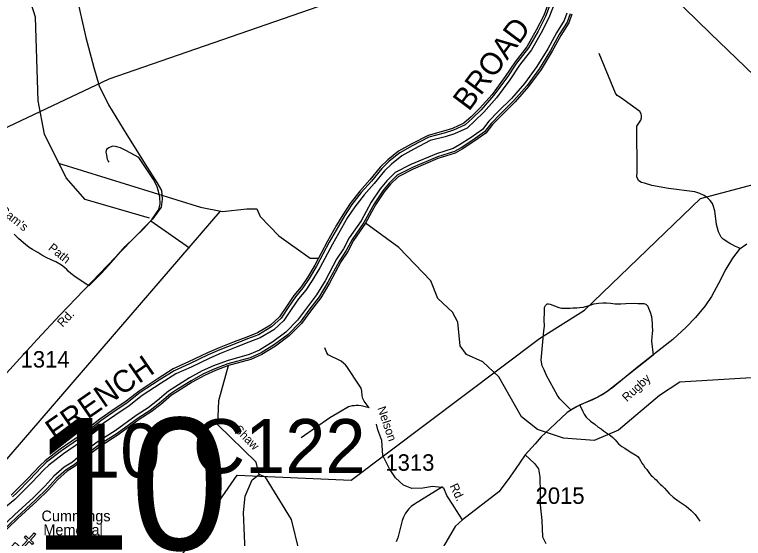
# Model space of a CAD drawing. Extents: x 884530 to 1028605, y 526725 to 653634.
# Drawn here: x 938802 to 944336, y 599486 to 603462 of the extents above; entities that cross this region are included whole.
import ezdxf

# ---------------------------------------------------------------- set-up
doc = ezdxf.new("R2010")
doc.units = 0
for name, color, linetype in [('Exist Cultural Church CELL', 7, 'Continuous'), ('Exist Cultural Church Label', 7, 'Continuous'), ('Exist Hydrographic Bay Label', 7, 'Continuous'), ('Exist Hydrographic Buffer Line', 7, 'Continuous'), ('Exist Hydrographic Creek Single Shore', 7, 'Continuous'), ('Exist Hydrographic Creek Single Shore Label', 7, 'Continuous'), ('Exist Hydrographic Misc Water Feature', 7, 'Continuous'), ('Exist Hydrographic River Shore Label', 7, 'Continuous'), ('Exist Road Non-System Type 51', 7, 'Continuous'), ('Exist Road Non-System Type 51 Label', 7, 'Continuous'), ('Exist Road Secondary Structure Culvert Number Label', 7, 'Continuous'), ('Exist Road Secondary Structure Standard Bridge Number Label', 7, 'Continuous'), ('Exist Road Secondary Type 51 Attributed', 7, 'Continuous'), ('Exist Road Secondary Type 51 Label', 7, 'Continuous'), ('Exist Road Secondary Type 51 Number Label', 7, 'Continuous'), ('Exist Utilities Electrical Transmission Line', 7, 'Continuous'), ('Raster_Level_0', 7, 'Continuous')]:
    doc.layers.add(name, color=color, linetype=linetype)

msp = doc.modelspace()

# ---------------------------------------------------------------- linework, layer by layer
at = {"layer": 'Exist Cultural Church CELL'}
msp.add_lwpolyline([(938806.1, 599454.1), (938848.2, 599415.8), (938899.6, 599472), (938876, 599493.6), (938886.8, 599505.4), (938910.4, 599483.8), (938951, 599528.2), (938962.8, 599517.4), (938922.2, 599473), (938945.8, 599451.4), (938935.1, 599439.6), (938911.4, 599461.2), (938860.1, 599405), (938902.6, 599366), (938830.7, 599287.4), (938734.3, 599375.6)], close=True, dxfattribs=at)
at = {"layer": 'Exist Hydrographic Bay Label'}
for points in [[(942861.5, 603565), (942819.8, 603453.8), (942762.7, 603343.9), (942692.1, 603217.6), (942601.5, 603102.1), (942527.5, 602990.4), (942427.4, 602856.1), (942332.8, 602749.4), (942267.9, 602686.1), (942213.6, 602636.6), (942127.9, 602597.6), (942059, 602576), (941941.6, 602544.9), (941813.5, 602478.9), (941717.2, 602424.3), (941636.5, 602359.4), (941578.7, 602303.5), (941498.9, 602207.1), (941422.8, 602120.4), (941350.6, 602028.5), (941294.4, 601942.8), (941247.1, 601862.9), (941178.3, 601741.3)], [(943033.2, 603463.6), (943009.1, 603399.1), (942948.9, 603303.8), (942882.9, 603183.3), (942799, 603045.3), (942704.2, 602914.9), (942602.3, 602799.4), (942500.1, 602698.6), (942431.4, 602626.6), (942380.3, 602562.1), (942290, 602497.7), (942200.2, 602439.3), (942147.6, 602410.6), (942015.8, 602368.8)], [(942015.8, 602368.8), (941827.5, 602288.9), (941714.9, 602231.1), (941655.8, 602174), (941608, 602116.1), (941542.9, 602017.7), (941466.1, 601878.1)], [(941466.1, 601878.1), (941376, 601747.8), (941331.1, 601663.7), (941280, 601585.9), (941192.4, 601422.9), (941126.1, 601312.9), (941055.2, 601221.3), (940980.1, 601117.5), (940887.4, 601022.4), (940783.2, 600945.9), (940680, 600881.6), (940594.5, 600844.6), (940425.3, 600797.4)], [(941178.3, 601741.3), (941081.9, 601560.8), (941025.9, 601466.5), (940978, 601395.7), (940922.1, 601328.5), (940872.4, 601253.7), (940813, 601168.2), (940744.3, 601104), (940646.7, 601045.7), (940565.7, 601014), (940469.8, 600976.6), (940354.3, 600931.5), (940265.4, 600893.5), (940123.3, 600825.3), (940005.9, 600771.9), (939891.2, 600699.5), (939746.7, 600604.5), (939647.9, 600526.3), (939539.5, 600454.2), (939448.5, 600391.1), (939354.4, 600317.3), (939277.2, 600251.1), (939148.7, 600162.3), (939032.8, 600075.2), (938994.1, 600036.3), (938903.2, 599940.9), (938809.9, 599846.1), (938775.8, 599813.7)], [(940425.3, 600797.4), (940326.5, 600759.7), (940243.3, 600723.3), (940149.5, 600671.3), (940038.4, 600602), (939993.3, 600572.8), (939911.6, 600503.2), (939837.8, 600445.4), (939747.2, 600387.9), (939587.1, 600271.7), (939451.7, 600184), (939359.3, 600114.9), (939263, 600034.4), (939201.4, 599996.6), (939127, 599930.4), (939058.5, 599855), (938970.7, 599767.7), (938826.9, 599636.4), (938666.3, 599486.3)]]:
    msp.add_lwpolyline(points, dxfattribs=at)
at = {"layer": 'Exist Hydrographic Buffer Line'}
for points in [[(942876.2, 603560.8), (942833.7, 603447.6), (942776.1, 603336.7), (942704.8, 603209.1), (942613.8, 603093.2), (942540, 602981.7), (942439.3, 602846.5), (942343.9, 602738.9), (942278.4, 602675), (942222, 602623.7), (942133.3, 602583.3), (942063.3, 602561.4), (941947.1, 602530.6), (941820.8, 602465.5), (941725.8, 602411.7), (941646.6, 602348), (941589.8, 602293.2), (941510.5, 602197.2), (941434.5, 602110.7), (941362.9, 602019.6), (941307.3, 601934.7), (941260.3, 601855.3), (941191.5, 601733.8)], [(942902.7, 603553.1), (942858.9, 603436.4), (942800.3, 603323.6), (942727.8, 603193.8), (942636.2, 603077.1), (942562.5, 602965.8), (942460.6, 602829.1), (942363.8, 602719.9), (942297.2, 602655), (942237.4, 602600.5), (942143.2, 602557.5), (942070.9, 602534.9), (941957.1, 602504.8), (941833.9, 602441.3), (941741.3, 602388.8), (941664.8, 602327.3), (941610.1, 602274.4), (941531.5, 602179.4), (941455.7, 602093.1), (941385.3, 602003.5), (941330.7, 601920.2), (941284.1, 601841.5), (941215.5, 601720.2)], [(942995.4, 603472.3), (942974.5, 603416.3), (942915.7, 603323.4), (942849.6, 603202.6), (942767, 603066.7), (942674.1, 602939), (942574.3, 602825.8), (942472.6, 602725.6), (942402.3, 602651.9), (942353.5, 602590.3), (942268.3, 602529.6), (942180.5, 602472.4), (942132.4, 602446.2), (942004.2, 602405.5)], [(943020, 603466.6), (942997, 603405.2), (942937.3, 603310.6), (942871.3, 603190), (942787.8, 603052.8), (942693.7, 602923.3), (942592.5, 602808.6), (942490.5, 602708), (942421.2, 602635.5), (942370.9, 602572), (942282.4, 602508.9), (942193.3, 602450.9), (942142.2, 602423.1), (942011.7, 602381.7)], [(942004.2, 602405.5), (941811.2, 602323.7), (941692.3, 602262.6), (941627.6, 602200.1), (941577.1, 602139), (941510, 602037.6), (941432.5, 601896.6)], [(942011.7, 602381.7), (941821.8, 602301.1), (941707, 602242.1), (941645.9, 602183.2), (941597.2, 602124.1), (941531.4, 602024.7), (941454.4, 601884.6)], [(941432.5, 601896.6), (941343.4, 601767.7), (941298.3, 601683.2), (941247.2, 601605.5), (941159.2, 601441.8), (941094.6, 601334.5), (941024.6, 601244.1), (940950.9, 601142.1), (940862.3, 601051.3), (940761.8, 600977.5), (940662.2, 600915.5), (940581.8, 600880.6), (940415.1, 600834.1)], [(941454.4, 601884.6), (941364.6, 601754.7), (941319.7, 601670.5), (941268.5, 601592.8), (941180.8, 601429.5), (941115.1, 601320.4), (941044.5, 601229.3), (940969.9, 601126.1), (940878.6, 601032.5), (940775.7, 600957), (940673.8, 600893.5), (940590.1, 600857.2), (940421.7, 600810.3)], [(941215.5, 601720.2), (941119.1, 601539.8), (941062, 601443.6), (941012.2, 601370), (940956.5, 601303), (940907.8, 601229.7), (940845.5, 601140.1), (940770.1, 601069.7), (940665.6, 601007.2), (940581.3, 600974.2), (940485.4, 600936.8), (940370.5, 600891.9), (940283, 600854.5), (940141.4, 600786.6), (940026.3, 600734.2), (939914.3, 600663.6), (939771.7, 600569.8), (939673, 600491.7), (939563.5, 600418.8), (939473.8, 600356.7), (939381.5, 600284.2), (939303.3, 600217.2), (939173.8, 600127.6), (939061, 600042.9), (939024.7, 600006.5), (938933.9, 599911.2), (938839.8, 599815.7), (938804.1, 599781.7), (938733.8, 599723.9)], [(941191.5, 601733.8), (941095.2, 601553.3), (941038.7, 601458.4), (940990.2, 601386.6), (940934.4, 601319.4), (940885, 601245.2), (940824.6, 601158.2), (940753.5, 601091.8), (940653.4, 601032), (940571.3, 600999.9), (940475.4, 600962.4), (940360.1, 600917.4), (940271.6, 600879.6), (940129.7, 600811.5), (940013.2, 600758.4), (939899.4, 600686.7), (939755.6, 600592.1), (939656.8, 600514), (939548.1, 600441.6), (939457.5, 600378.8), (939364, 600305.5), (939286.5, 600239), (939157.7, 600150), (939042.9, 600063.7), (939005, 600025.7), (938914.1, 599930.3), (938820.5, 599835.3), (938785.8, 599802.3)], [(940415.1, 600834.1), (940312.1, 600794.9), (940226.4, 600757.4), (940130.2, 600704.1), (940018.1, 600634), (939970.6, 600603.3), (939887.6, 600532.6), (939815.8, 600476.5), (939725.8, 600419.3), (939565.6, 600303), (939429.9, 600215.2), (939335.8, 600144.7), (939240.8, 600065.4), (939178.6, 600027.2), (939100.3, 599957.4), (939031, 599881.3), (938944.5, 599795.2), (938801.1, 599664.3), (938640.3, 599514)], [(940421.7, 600810.3), (940321.4, 600772), (940237.4, 600735.3), (940142.7, 600682.8), (940031.3, 600613.2), (939985.3, 600583.4), (939903.2, 600513.5), (939830.1, 600456.3), (939739.7, 600398.9), (939579.6, 600282.7), (939444.1, 600194.9), (939351.1, 600125.3), (939255.3, 600045.3), (939193.4, 600007.3), (939117.7, 599939.9), (939048.9, 599864.2), (938961.5, 599777.4), (938817.9, 599646.1), (938657.2, 599496)]]:
    msp.add_lwpolyline(points, dxfattribs=at)
at = {"layer": 'Exist Hydrographic Creek Single Shore'}
for points in [[(939825.1, 601917.1), (939337.3, 602058.3), (939192.9, 602222), (939029.8, 602553.5), (938980.6, 602807.1), (938961.5, 603440.8), (938894, 603652.3), (938832, 603778.2), (938607.9, 604045.2), (938502.2, 604122.8), (938083.6, 604305.1), (937355.4, 604457.6), (937085.2, 604600.9), (936893.6, 604608), (936597, 604709.1), (936265.2, 604755.1), (935718.2, 605081.2), (935429.2, 605159.1), (934980.7, 605443.8)], [(939136, 602334.5), (940213.1, 602000.5), (940380, 601967.9), (940564.9, 601986), (940641.1, 601986), (940666.5, 601927.9), (940807.9, 601782.8), (941047.3, 601612.2), (941109, 601612.2)], [(938351.1, 599435.9), (938336.6, 599483.1), (938348.1, 599555), (938392.5, 599626.4), (938476.5, 599748.7), (938552.7, 599868.4), (940361.8, 601967.9)], [(939836, 601895.3), (940129.7, 601692)], [(940657.9, 599971.4), (940636.1, 600063.8), (940346.2, 600348.6), (940352.8, 600532.2), (940425.3, 600797.4)], [(940429.8, 596868.3), (940324.6, 597254.9), (940338.4, 597415.5), (940395.8, 597602.9), (940409.7, 597959.7), (940469.1, 598102), (940505.2, 598274.7), (940595.9, 598501.9), (940777.7, 598680.5), (940766.9, 598844.5), (940667.6, 598940), (940567, 599088.4), (940554.5, 599328.8), (940539, 599681.8), (940552.1, 599806.3), (940606.4, 599929.8), (940657.9, 599971.4)], [(944279.7, 596872.5), (944318.7, 597024.5), (944253.6, 597146.1), (944101.8, 597241.7), (943949.9, 597385), (943798, 597493.6), (943706.8, 597541.4), (942989.5, 597531.4), (942717.5, 597642.9), (942524.9, 597864), (942441.8, 597941.5), (942072.2, 598253), (941833, 598326.8), (941457.7, 598586.1), (941261.4, 598801.3), (941111.8, 598983.8), (940962.3, 599391.1), (940904.1, 599628.5), (940707.4, 599950.8), (940657.9, 599971.4)]]:
    msp.add_lwpolyline(points, dxfattribs=at)
at = {"layer": 'Exist Hydrographic Misc Water Feature'}
msp.add_lwpolyline([(944394.9, 600703.7), (943851.9, 600672), (943698.1, 600570), (943388.3, 600307.1), (943202.3, 600228.8), (942969.3, 600246.7), (942771.6, 600313), (942649.8, 600407.3), (942477.5, 600712.7), (942356.3, 600826.7), (942233.3, 600881.7), (942185.6, 600948.2), (942166.9, 601125.8), (942128, 601202.1), (942015, 601306.1), (941961.5, 601441.8), (941720.2, 601692.7), (941466.1, 601878.1)], dxfattribs=at)
at = {"layer": 'Exist Road Non-System Type 51'}
for points in [[(944312.7, 601686.7), (944275.4, 601701.6), (944253.8, 601712.9), (944231.8, 601725), (944182.1, 601758), (944167, 601772.9), (944156, 601793), (944146.5, 601813.5), (944132.5, 601867.7), (944118.8, 601971.5), (944105.2, 602012.3), (944100, 602028), (944083.3, 602050), (944062.1, 602070.1), (944038.2, 602087.8), (944005.7, 602102.4), (943965.9, 602115), (943766.9, 602142.2), (943639, 602164.2), (943583.6, 602180.9), (943561.5, 602188.3), (943542.7, 602199.8), (943531.3, 602217.7), (943525.9, 602231.3), (943528, 602268), (943526.9, 602614.8), (943557.1, 602660.4), (943561.3, 602677.5), (943561.3, 602692.6), (943559.8, 602707.5), (943548.8, 602725.4), (943402.9, 602833.1), (943377.5, 602846.5), (943364, 602864.5), (943239.9, 603164.9)], [(939744.7, 602376.8), (939647.5, 602430.8), (939619.9, 602441.7), (939605.8, 602449.6), (939586.8, 602455.9), (939567.1, 602459.9), (939545.9, 602462.2), (939516.8, 602450.5), (939500.7, 602436.5), (939497.4, 602429.9), (939495.5, 602418.1), (939496.3, 602407.1), (939499.4, 602393.7), (939503.3, 602377.2), (939505, 602364.5), (939510.4, 602355.1), (939512.8, 602348.8), (939516.8, 602341)], [(939366, 601403.7), (939458.7, 601497.1), (939517.9, 601559.8), (939641.5, 601701.2), (939781.9, 601838), (939845.5, 601910), (939896.6, 601981.4), (939907.3, 602024.1), (939905.2, 602076.2), (939895.5, 602121.6), (939880.6, 602162), (939855.8, 602210.3), (939744.7, 602376.8)], [(939366, 601403.7), (939262, 601472.3), (939228.4, 601496.1), (939207.6, 601515), (939197.7, 601526.4), (939181.4, 601541.8), (939158.3, 601559.5), (939113.9, 601585.7), (939078.5, 601601.3), (939042.3, 601617.6), (939009.7, 601636.3), (938978.1, 601655.8), (938955.2, 601669.3), (938937.9, 601679.2), (938913.7, 601694.7), (938883.5, 601716.3), (938834.1, 601758.9), (938799.8, 601794.2)], [(943025.7, 600462.1), (942966.7, 600518.7), (942941.3, 600546.3), (942923, 600571.6), (942840.2, 600723.2), (942821.9, 600764.6), (942808.1, 600794.5), (942801.2, 600838.1), (942821.4, 601060.1), (942824.1, 601095.5), (942822.2, 601143.5), (942821.9, 601150.6), (942824.1, 601196.6), (942826.4, 601237.9), (942831.8, 601253.1), (942844.9, 601265.6), (942855.6, 601266.6), (942868.5, 601264.2), (942934, 601237.4), (942943.4, 601235.4), (942955.6, 601233.4), (943019.5, 601233.4), (943040.2, 601235.7), (943060.8, 601235.3), (943070.1, 601235.7), (943092.3, 601237.8), (943120.2, 601241), (943164.5, 601252.5), (943200.7, 601267), (943234.4, 601272.2), (943268.1, 601274.7), (943296.6, 601274.7), (943325.2, 601272.2), (943362.2, 601267.2), (943404.5, 601267), (943443.2, 601267.6), (943508.7, 601270.6), (943533.6, 601269.7), (943556.8, 601269.2), (943580, 601268.5), (943593.7, 601263.9), (943602.9, 601256.8), (943609.6, 601248), (943615.3, 601232.5), (943627.8, 601203.5), (943636.6, 601170.4), (943641.1, 601142.7), (943642.3, 601119), (943642.5, 601094.4), (943644.5, 601065.7), (943642.6, 601038.8), (943641.1, 601018.1), (943637.9, 600983.2), (943650.6, 600876.8)], [(941494.1, 600477.2), (941455.4, 600528.3), (941445.8, 600547), (941439.7, 600566.7), (941438.6, 600604.2), (941432.9, 600624.9), (941424.4, 600642), (941324.9, 600790.2), (941313.4, 600804.2), (941301.3, 600813.7), (941280.5, 600830.2), (941262.4, 600839.9), (941201.8, 600868.1), (941181.8, 600880.3), (941171.7, 600893.9), (941157.5, 600931.1)], [(943650.6, 600876.8), (943393.6, 600673.1), (943333.3, 600624.9), (943299.4, 600597.8), (943259.4, 600574.4), (943229.9, 600558.5), (943190, 600541.2), (943144, 600520.9), (943094.6, 600498)], [(941494.1, 600477.2), (941433.6, 600491.9), (941412.8, 600493.3), (941394.2, 600494), (941380, 600492.6), (941365.6, 600491.1), (941355.7, 600489.7), (941337.7, 600483.3), (941268.7, 600445.2), (941255.6, 600437.5), (941194.2, 600400.5), (940976.9, 600249.9)], [(943094.6, 600498), (943061.8, 600483.1), (943025.7, 600462.1)], [(943094.6, 600498), (943115.2, 600447.8), (943125.7, 600427.8), (943141.2, 600406.9), (943174.9, 600375.3), (943207.7, 600351.8), (943233.2, 600331.2), (943254.9, 600317.3), (943272.2, 600303), (943325.6, 600266.6), (943343.9, 600252.5), (943361.9, 600232.9), (943386, 600202.7), (943412.3, 600183.1), (943435, 600169.6), (943476.4, 600143.2), (943518.7, 600118.3), (943533, 600106.2), (943546.5, 600088.9), (943556.4, 600071.5), (943565.4, 600056.5), (943577.5, 600040.6), (943588.1, 600024.1), (943601.6, 600008.2), (943613, 599993.1), (943621.9, 599978), (943634, 599964.5), (943645.3, 599955.4), (943660.5, 599940.4), (943673.5, 599930.9), (943686.7, 599915.4), (943703.9, 599897.9), (943719.2, 599883.6), (943735.8, 599866.5), (943772, 599827.3), (943802.9, 599798.6), (943841.3, 599771.5), (943900.9, 599730.8), (943937.8, 599698.4), (943970.3, 599666.8), (944004.8, 599616.6)], [(942049.8, 599877.2), (941837.1, 599744.9), (941813, 599728.6), (941795.3, 599709.3), (941770.8, 599676.9), (941762.6, 599663.4), (941753.6, 599646), (941744, 599622), (941712.8, 599489.3), (941698.4, 599459.7)]]:
    msp.add_lwpolyline(points, dxfattribs=at)
at = {"layer": 'Exist Road Secondary Type 51 Attributed'}
for points in [[(939270.6, 603612.8), (939342.5, 603288.1), (939402.9, 603060.3), (939444.7, 602920.9), (939514.3, 602776.8), (939653.7, 602549), (939811.6, 602298), (939881.3, 602186.5), (939918.5, 602126.1), (939923.1, 602061), (939913.8, 602000.6), (939848.8, 601907.6), (939686.2, 601744.9), (939148.5, 601181.7), (938972, 600995.8), (938605.1, 600596), (938317.1, 600289.3), (938173.1, 600154.5), (938089.5, 600038.3), (938033.7, 599940.7), (938033.7, 599843.1), (938052.3, 599768.7), (938103.1, 599712.8)], [(944360.4, 601719.1), (944302.5, 601678.2), (944252.6, 601613.6), (944201.7, 601529.3), (944145.7, 601421.5), (944093.5, 601322.8), (944044.5, 601250.2), (943971.5, 601162.4), (943901.4, 601089), (943799.5, 600996.6), (943661.4, 600886.8), (943529.5, 600783.4), (943418.1, 600690.7), (943343.5, 600631), (943267.6, 600577.4), (943184.2, 600535.1), (943095.9, 600499), (943038.6, 600465.8), (942997.4, 600440.4), (942866.3, 600317.9), (942800.5, 600257.2), (942754.3, 600203.4), (942679, 600121)], [(942203, 599627.6), (942156.9, 599697.7), (942131.4, 599737.5), (942084.6, 599810.2), (942061.8, 599867.6), (942044.2, 599871.1), (941974.1, 599880.4), (941901.1, 599867.6), (941818.4, 599864.4), (941754.7, 599889.8), (941694.5, 599945.4), (941649.6, 600013.2), (941598.5, 600115.3), (941589, 600228.5), (941559, 600310.9), (941549.5, 600352.7)], [(942679, 600121), (942601.6, 600007.9), (942549.2, 599932.5), (942478.1, 599838.2), (942203, 599627.6)], [(942679, 600121), (942750.2, 600054), (942780.4, 600013.7), (942790, 599954.1), (942792.2, 599832.9), (942792, 599739.6), (942804.7, 599622.4), (942810.9, 599496.7), (942834.3, 599447.8)], [(942203, 599627.6), (942147.4, 599575.1), (942069.5, 599442), (941659.1, 598704.2)]]:
    msp.add_lwpolyline(points, dxfattribs=at)
at = {"layer": 'Exist Utilities Electrical Transmission Line'}
for points in [[(943294.3, 604092.8), (944085.4, 603316.9), (944615.6, 602810), (945388.4, 602660.6), (945635.4, 602622.8), (947741.4, 602188.1), (949389.7, 601845.2), (950956.8, 601506.5), (952029.7, 601789.5), (953375.6, 602156.3), (954224.7, 603631.8)], [(940066.7, 599140.6), (940064.4, 599348.1), (940490.6, 599965.6), (941357.5, 599928.5), (942787.5, 601002.5), (943129.6, 601218.7), (944010.3, 602066.1), (945543.5, 602473.7), (945955.5, 602579.7), (946234.5, 602634.4), (946768.5, 602749.7), (947806.7, 602791.9), (948025.7, 602913.5), (948456.6, 603716.1)], [(938516.5, 602500.6), (939519.3, 602974), (941106.5, 603523.7)]]:
    msp.add_lwpolyline(points, dxfattribs=at)

# ---------------------------------------------------------------- texts
at = {"layer": 'Exist Cultural Church Label'}
for s, p in [('Cummings', (939006.1, 599615.2)), ('Memorial', (939020.5, 599509.5))]:
    msp.add_text(s, height=82.02, dxfattribs=at).set_placement(p)
at = {"layer": 'Exist Hydrographic Creek Single Shore Label'}
msp.add_text('Shaw', height=65.62, rotation=314.8621, dxfattribs=at).set_placement((940465.4, 600306.2))
msp.add_text('Shaw', height=65.62, rotation=314.8621, dxfattribs=at).set_placement((940465.4, 600306.2))
at = {"layer": 'Exist Hydrographic River Shore Label'}
for s, rotation, p in [('BROAD', 53.2108, (942251.3, 602721.5)), ('BROAD', 53.2108, (942251.3, 602721.5)), ('FRENCH', 34.7252, (939111.2, 600217.2)), ('FRENCH', 34.7252, (939111.2, 600217.2))]:
    msp.add_text(s, height=167.32, rotation=rotation, dxfattribs=at).set_placement(p)
at = {"layer": 'Exist Road Non-System Type 51 Label'}
for s, p in [("Cam's", (938681, 601966.9)), ('Path', (939052.5, 601680.9))]:
    msp.add_text(s, height=65.62, rotation=321.1656, dxfattribs=at).set_placement(p)
at = {"layer": 'Exist Road Secondary Structure Culvert Number Label'}
msp.add_text('C122', height=410.1, dxfattribs=at).set_placement((940155.9, 599981.2))
at = {"layer": 'Exist Road Secondary Structure Standard Bridge Number Label'}
msp.add_text('10', height=410.1, dxfattribs=at).set_placement((939299.2, 599947))
at = {"layer": 'Exist Road Secondary Type 51 Label'}
for s, rotation, p in [('Rd.', 46.2351, (939166.1, 601084.9)), ('Rugby', 42.8933, (943450.8, 600519)), ('Nelson', 288.7873, (941555.4, 600475.1)), ('Rd.', 295.208, (942104.1, 599884.3))]:
    msp.add_text(s, height=65.62, rotation=rotation, dxfattribs=at).set_placement(p)
at = {"layer": 'Exist Road Secondary Type 51 Number Label'}
for s, p in [('1314', (938847.3, 600782.6)), ('1313', (941617.5, 599999.3)), ('2015', (942757.7, 599747.9))]:
    msp.add_text(s, height=125, dxfattribs=at).set_placement(p)
at = {"layer": 'Raster_Level_0'}
msp.add_text('10', height=1000, dxfattribs=at).set_placement((938938.5, 599399.3))

doc.saveas('drawing.dxf')
